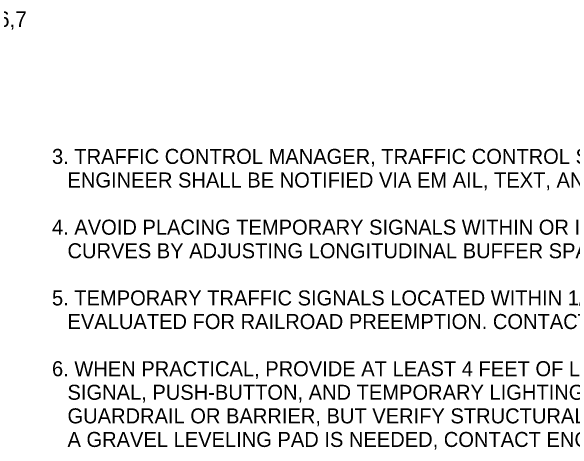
# Model space of a CAD drawing. Extents: x 99976 to 100136, y 99905 to 100011.
# Drawn here: x 100049.858 to 100052.474, y 99912.907 to 99914.95 of the extents above; entities that cross this region are included whole.
import ezdxf

# ---------------------------------------------------------------- set-up
doc = ezdxf.new("R2010")
doc.units = 0
doc.layers.add('SH_GI_GeneralNotesBodyText', color=7, linetype='Continuous')
doc.layers.add('TR_SN_ConstructionSigns', color=7, linetype='Continuous')

msp = doc.modelspace()

# ---------------------------------------------------------------- texts
at = {"layer": 'SH_GI_GeneralNotesBodyText'}
for s, p in [('3. TRAFFIC CONTROL MANAGER, TRAFFIC CONTROL SUPERVISOR (PRIMARY AND ALTERNATE), AND WSDOT ', (100050.0475, 99914.2384)), ('ENGINEER SHALL BE NOTIFIED VIA EM AIL, TEXT, AND/OR PAGE IF ANY TEMPORARY SIGNAL MALFUNCTIONS.', (100050.1197, 99914.1285)), ('4. AVOID PLACING TEMPORARY SIGNALS WITHIN OR IMMEDIATELY FOLLOWING HORIZONTAL & VERTICAL ', (100050.0475, 99913.9087)), ('CURVES BY ADJUSTING LONGITUDINAL BUFFER SPACE OR EXTENDING WORK AREA.', (100050.1197, 99913.7988)), ('5. TEMPORARY TRAFFIC SIGNALS LOCATED WITHIN 1/4 MILE OF A RAILROAD GRADE CROSSING SHALL BE ', (100050.0475, 99913.579)), ('EVALUATED FOR RAILROAD PREEMPTION. CONTACT REGION TRANSPORTATION OPERATIONS.', (100050.1197, 99913.4691)), ('6. WHEN PRACTICAL, PROVIDE AT LEAST 4 FEET OF LATERAL CLEARANCE FROM TRAVEL LANE TO TEMP ', (100050.0475, 99913.2493)), ('SIGNAL, PUSH-BUTTON, AND TEMPORARY LIGHTING.  ACCEPTABLE TO PLACE THESE DEVICES BEHIND EXISTING ', (100050.1197, 99913.1394)), ('GUARDRAIL OR BARRIER, BUT VERIFY STRUCTURAL LOADING ON TEMP SIGNAL MAST ARM IS SUFFICIENT.  IF ', (100050.1197, 99913.0295)), ('A GRAVEL LEVELING PAD IS NEEDED, CONTACT ENGINEER PRIOR TO INSTALLING.', (100050.1197, 99912.9196))]:
    msp.add_text(s, height=0.07, rotation=360, dxfattribs=at).set_placement(p)
at = {"layer": 'TR_SN_ConstructionSigns'}
msp.add_text('SEE NOTES 1,6,7', height=0.072, rotation=360, dxfattribs=at).set_placement((100049.138, 99914.8768))

doc.saveas('drawing.dxf')
